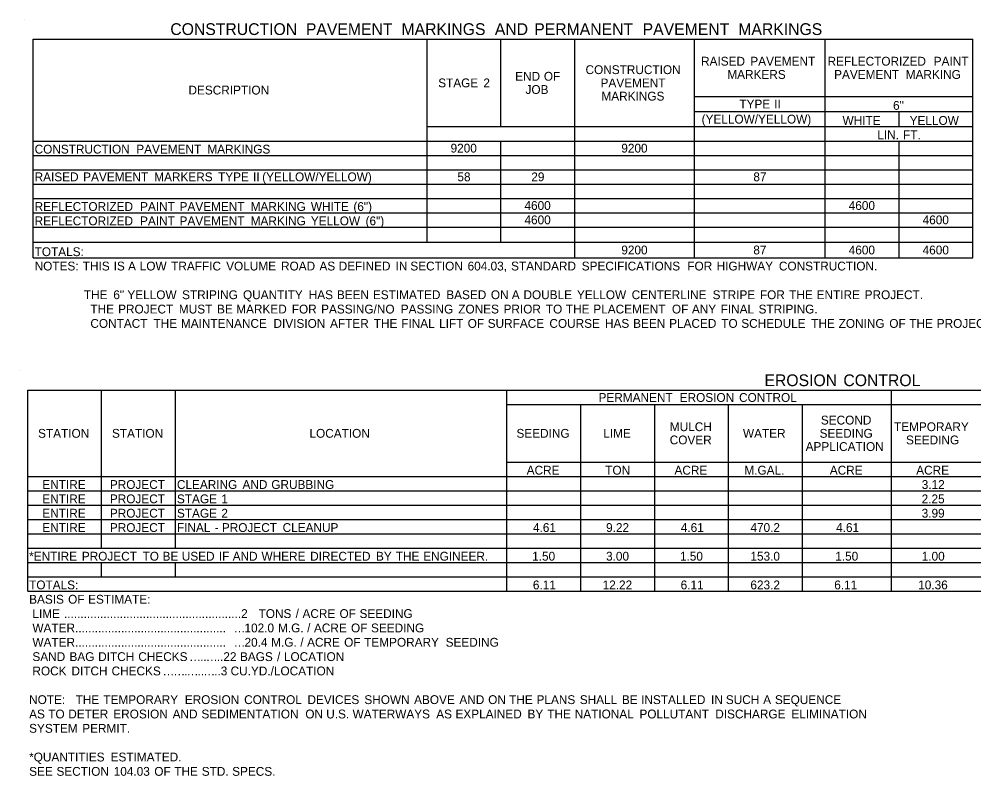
# Model space of a CAD drawing. Extents: x 1940653 to 1945779, y 534266 to 535271.
# Drawn here: x 1940655 to 1941239, y 534297 to 534760 of the extents above; entities that cross this region are included whole.
import ezdxf

# ---------------------------------------------------------------- set-up
doc = ezdxf.new("R2010")
doc.units = 0
doc.layers.add('Default', color=7, linetype='Continuous')
doc.layers.add('R_Logo', color=7, linetype='Continuous')

msp = doc.modelspace()

# ---------------------------------------------------------------- linework, layer by layer
at = {"layer": 'Default'}
for p, q in [((1940663.72, 534748.03), (1941238.48, 534748.03)), ((1940663.72, 534614.21), (1940663.72, 534748.03)), ((1940663.72, 534614.21), (1940663.72, 534748.03)), ((1940904.59, 534623.86), (1940904.59, 534748.03)), ((1940949.78, 534694.5), (1940949.78, 534748.03)), ((1940994.97, 534614.21), (1940994.97, 534748.03)), ((1941068.24, 534614.21), (1941068.24, 534748.03)), ((1941148.1, 534614.21), (1941148.1, 534748.03)), ((1941238.48, 534614.21), (1941238.48, 534748.03)), ((1941068.24, 534712.93), (1941238.48, 534712.93)), ((1941068.24, 534703.71), (1941238.48, 534703.71)), ((1941193.29, 534694.5), (1941193.29, 534703.71)), ((1940904.59, 534694.5), (1941238.48, 534694.5)), ((1940904.59, 534623.86), (1940904.59, 534694.5)), ((1940994.97, 534614.21), (1940994.97, 534694.5)), ((1941068.24, 534614.21), (1941068.24, 534694.5)), ((1940663.72, 534685.72), (1941238.48, 534685.72)), ((1940949.78, 534623.86), (1940949.78, 534685.72)), ((1940949.78, 534623.86), (1940949.78, 534685.72)), ((1941148.1, 534614.21), (1941148.1, 534685.72)), ((1941193.29, 534614.21), (1941193.29, 534685.72)), ((1941193.29, 534614.21), (1941193.29, 534685.72)), ((1940663.72, 534676.95), (1941238.48, 534676.95)), ((1940663.72, 534668.17), (1941238.48, 534668.17)), ((1940663.72, 534659.4), (1941238.48, 534659.4)), ((1940663.72, 534650.62), (1941238.48, 534650.62)), ((1940663.72, 534641.85), (1941238.48, 534641.85)), ((1940663.72, 534633.07), (1941238.48, 534633.07)), ((1940663.72, 534623.86), (1941238.48, 534623.86)), ((1940663.72, 534614.21), (1941238.48, 534614.21)), ((1940660.36, 534533.19), (1941659.39, 534533.19)), ((1940660.36, 534410.34), (1940660.36, 534533.19)), ((1940660.36, 534410.34), (1940660.36, 534533.19)), ((1940705.55, 534436.66), (1940705.55, 534533.19)), ((1940750.74, 534436.66), (1940750.74, 534533.19)), ((1940953.44, 534410.34), (1940953.44, 534533.19)), ((1941188.61, 534524.41), (1941188.61, 534533.19)), ((1941188.61, 534410.34), (1941188.61, 534533.19)), ((1940953.44, 534524.41), (1941659.39, 534524.41)), ((1940998.63, 534410.34), (1940998.63, 534524.41)), ((1941043.82, 534410.34), (1941043.82, 534524.41)), ((1941089.02, 534410.34), (1941089.02, 534524.41)), ((1941134.21, 534410.34), (1941134.21, 534524.41)), ((1940953.44, 534489.31), (1941545.75, 534489.31)), ((1940998.63, 534410.34), (1940998.63, 534489.31)), ((1941043.82, 534419.11), (1941043.82, 534489.31)), ((1941089.02, 534419.11), (1941089.02, 534489.31)), ((1941134.21, 534419.11), (1941134.21, 534489.31)), ((1941188.61, 534419.11), (1941188.61, 534489.31)), ((1940660.36, 534480.54), (1941659.39, 534480.54)), ((1940705.55, 534436.66), (1940705.55, 534480.54)), ((1940750.74, 534436.66), (1940750.74, 534480.54)), ((1940953.44, 534436.66), (1940953.44, 534480.54)), ((1940660.36, 534471.76), (1941659.39, 534471.76)), ((1940660.36, 534462.99), (1941659.39, 534462.99)), ((1940660.36, 534454.21), (1941659.39, 534454.21)), ((1940660.36, 534445.44), (1941659.39, 534445.44)), ((1940660.36, 534436.66), (1941659.39, 534436.66)), ((1940660.36, 534427.89), (1941659.39, 534427.89)), ((1940705.55, 534419.11), (1940705.55, 534427.89)), ((1940705.55, 534419.11), (1940705.55, 534427.89)), ((1940750.74, 534419.11), (1940750.74, 534427.89)), ((1940750.74, 534419.11), (1940750.74, 534427.89)), ((1940953.44, 534410.34), (1940953.44, 534427.89)), ((1940660.36, 534419.11), (1941188.61, 534419.11)), ((1940998.63, 534419.11), (1941188.61, 534419.11)), ((1941188.61, 534419.11), (1941435.19, 534419.11)), ((1940660.36, 534410.34), (1941659.39, 534410.34))]:
    msp.add_line(p, q, dxfattribs=at)
at = {"layer": 'R_Logo'}
for p, q in [((1940658.45, 534760.31), (1940658.45, 534760.31)), ((1940655.09, 534545.47), (1940655.09, 534545.47))]:
    msp.add_line(p, q, dxfattribs=at)

# ---------------------------------------------------------------- texts
at = {"layer": 'Default'}
for s, height, p in [('CONSTRUCTION', 7.2, (1940747.58, 534750.57)), (' PAVEMENT', 7.2, (1940827.82, 534750.57)), (' MARKINGS', 7.2, (1940886.31, 534750.57)), (' AND', 7.2, (1940943.38, 534750.57)), (' PERMANENT', 7.2, (1940967.47, 534750.57)), (' PAVEMENT', 7.2, (1941033.78, 534750.57)), (' MARKINGS', 7.2, (1941092.27, 534750.57)), ('RAISED', 5.4, (1941072.17, 534731.83)), (' PAVEMENT', 5.4, (1941100.3, 534731.83)), ('REFLECTORIZED', 5.4, (1941149.54, 534731.83)), (' PAINT', 5.4, (1941212.46, 534731.83)), ('END', 5.4, (1940958.49, 534722.61)), (' OF', 5.4, (1940974.04, 534722.61)), ('CONSTRUCTION', 5.4, (1941001.52, 534726.66)), ('MARKERS', 5.4, (1941088.23, 534723.73)), ('PAVEMENT', 5.4, (1941153.56, 534723.73)), (' MARKING', 5.4, (1941195.33, 534723.73)), ('STAGE', 5.4, (1940911.42, 534718.56)), (' 2', 5.4, (1940937.04, 534718.56)), ('PAVEMENT', 5.4, (1941010.72, 534718.56)), ('DESCRIPTION', 5.4, (1940758.67, 534714.18)), ('JOB', 5.4, (1940964.81, 534714.51)), ('MARKINGS', 5.4, (1941011.25, 534710.46)), ('TYPE', 5.4, (1941095.6, 534705.62)), (' II', 5.4, (1941114.94, 534705.62)), ('6"', 5.4, (1941189.59, 534704.79)), ('(YELLOW/YELLOW)', 5.4, (1941072.53, 534696.41)), ('WHITE', 5.4, (1941158.72, 534695.58)), ('YELLOW', 5.4, (1941199.75, 534695.58)), ('LIN.', 5.4, (1941179.98, 534686.8)), (' FT.', 5.4, (1941193.71, 534686.8)), ('CONSTRUCTION', 5.4, (1940664.59, 534678.03)), (' PAVEMENT', 5.4, (1940724.76, 534678.03)), (' MARKINGS', 5.4, (1940768.21, 534678.03)), ('9200', 5.4, (1940918.98, 534678.64)), ('9200', 5.4, (1941023.4, 534678.64)), ('RAISED', 5.4, (1940664.59, 534661.09)), (' PAVEMENT', 5.4, (1940692.28, 534661.09)), (' MARKERS', 5.4, (1940735.74, 534661.09)), (' TYPE', 5.4, (1940774.76, 534661.09)), (' II', 5.4, (1940796.16, 534661.09)), (' (YELLOW/YELLOW)', 5.4, (1940801.77, 534661.09)), ('58', 5.4, (1940923.16, 534661.09)), ('29', 5.4, (1940968.35, 534661.09)), ('87', 5.4, (1941104.15, 534661.09)), ('REFLECTORIZED', 5.4, (1940664.59, 534642.93)), (' PAINT', 5.4, (1940727.08, 534642.93)), (' PAVEMENT', 5.4, (1940751.24, 534642.93)), (' MARKING', 5.4, (1940794.7, 534642.93)), (' WHITE', 5.4, (1940831.53, 534642.93)), (' (6")', 5.4, (1940857.53, 534642.93)), ('4600', 5.4, (1940964.17, 534643.54)), ('4600', 5.4, (1941162.48, 534643.54)), ('4600', 5.4, (1940964.17, 534634.76)), ('4600', 5.4, (1941207.68, 534634.76)), ('REFLECTORIZED', 5.4, (1940664.59, 534634.15)), (' PAINT', 5.4, (1940727.08, 534634.15)), (' PAVEMENT', 5.4, (1940751.24, 534634.15)), (' MARKING', 5.4, (1940794.7, 534634.15)), (' YELLOW', 5.4, (1940831.53, 534634.15)), (' (6")', 5.4, (1940864.99, 534634.15)), ('TOTALS:', 5.4, (1940664.59, 534615.29)), ('9200', 5.4, (1941023.4, 534616.33)), ('87', 5.4, (1941104.14, 534616.33)), ('4600', 5.4, (1941162.49, 534616.33)), ('4600', 5.4, (1941207.68, 534616.33)), ('NOTES:', 5.4, (1940664.59, 534606.51)), (' THIS', 5.4, (1940692.03, 534606.51)), (' IS', 5.4, (1940710.91, 534606.51)), (' A', 5.4, (1940719.74, 534606.51)), (' LOW', 5.4, (1940726.88, 534606.51)), (' TRAFFIC', 5.4, (1940746.08, 534606.51)), (' VOLUME', 5.4, (1940779.73, 534606.51)), (' ROAD', 5.4, (1940813.28, 534606.51)), (' AS', 5.4, (1940836.78, 534606.51)), (' DEFINED', 5.4, (1940848.54, 534606.51)), (' IN', 5.4, (1940883.36, 534606.51)), (' SECTION', 5.4, (1940892.38, 534606.51)), (' 604.03,', 5.4, (1940927.39, 534606.51)), (' STANDARD', 5.4, (1940953.98, 534606.51)), (' SPECIFICATIONS', 5.4, (1940997.18, 534606.51)), (' FOR', 5.4, (1941061.77, 534606.51)), (' HIGHWAY', 5.4, (1941079.69, 534606.51)), (' CONSTRUCTION.', 5.4, (1941117.78, 534606.51)), ('               THE', 5.4, (1940664.59, 534588.96)), (' 6"', 5.4, (1940710.71, 534588.96)), (' YELLOW', 5.4, (1940719.32, 534588.96)), (' STRIPING', 5.4, (1940752.78, 534588.96)), (' QUANTITY', 5.4, (1940790.03, 534588.96)), (' HAS', 5.4, (1940830.22, 534588.96)), (' BEEN', 5.4, (1940847.44, 534588.96)), (' ESTIMATED', 5.4, (1940869.46, 534588.96)), (' BASED', 5.4, (1940914.34, 534588.96)), (' ON', 5.4, (1940941.62, 534588.96)), (' A', 5.4, (1940954.41, 534588.96)), (' DOUBLE', 5.4, (1940961.55, 534588.96)), (' YELLOW', 5.4, (1940994.27, 534588.96)), (' CENTERLINE', 5.4, (1941027.73, 534588.96)), (' STRIPE', 5.4, (1941077.22, 534588.96)), (' FOR', 5.4, (1941106.16, 534588.96)), (' THE', 5.4, (1941124.08, 534588.96)), (' ENTIRE', 5.4, (1941140.87, 534588.96)), (' PROJECT.', 5.4, (1941170.23, 534588.96)), ('   THE', 5.4, (1940692.67, 534580.19)), (' PROJECT', 5.4, (1940713.65, 534580.19)), (' MUST', 5.4, (1940750.81, 534580.19)), (' BE', 5.4, (1940774.13, 534580.19)), (' MARKED', 5.4, (1940785.89, 534580.19)), (' FOR', 5.4, (1940819.87, 534580.19)), (' PASSING/NO', 5.4, (1940837.79, 534580.19)), (' PASSING', 5.4, (1940886.51, 534580.19)), (' ZONES', 5.4, (1940921.68, 534580.19)), (' PRIOR', 5.4, (1940949.37, 534580.19)), (' TO', 5.4, (1940975.26, 534580.19)), (' THE', 5.4, (1940987.5, 534580.19)), (' PLACEMENT', 5.4, (1941004.28, 534580.19)), (' OF', 5.4, (1941052.35, 534580.19)), (' ANY', 5.4, (1941064.57, 534580.19)), (' FINAL', 5.4, (1941082.13, 534580.19)), (' STRIPING.', 5.4, (1941105.34, 534580.19)), ('   CONTACT', 5.4, (1940692.67, 534571.41)), (' THE', 5.4, (1940735.28, 534571.41)), (' MAINTENANCE', 5.4, (1940752.06, 534571.41)), (' DIVISION', 5.4, (1940808.67, 534571.41)), (' AFTER', 5.4, (1940843.27, 534571.41)), (' THE', 5.4, (1940870, 534571.41)), (' FINAL', 5.4, (1940886.79, 534571.41)), (' LIFT', 5.4, (1940909.99, 534571.41)), (' OF', 5.4, (1940927.45, 534571.41)), (' SURFACE', 5.4, (1940939.67, 534571.41)), (' COURSE', 5.4, (1940977.42, 534571.41)), (' HAS', 5.4, (1941011.4, 534571.41)), (' BEEN', 5.4, (1941028.62, 534571.41)), (' PLACED', 5.4, (1941050.65, 534571.41)), (' TO', 5.4, (1941082.53, 534571.41)), (' SCHEDULE', 5.4, (1941094.77, 534571.41)), (' THE', 5.4, (1941137.55, 534571.41)), (' ZONING', 5.4, (1941154.34, 534571.41)), (' OF', 5.4, (1941185.3, 534571.41)), (' THE', 5.4, (1941197.53, 534571.41)), (' PROJECT.', 5.4, (1941214.31, 534571.41)), ('EROSION', 7.2, (1941110.96, 534535.73)), (' CONTROL', 7.2, (1941156.55, 534535.73)), ('PERMANENT', 5.4, (1941009.48, 534526.1)), (' EROSION', 5.4, (1941057.11, 534526.1)), (' CONTROL', 5.4, (1941093.4, 534526.1)), ('SECOND', 5.4, (1941145.45, 534512.26)), ('MULCH', 5.4, (1941053.09, 534508.21)), ('TEMPORARY', 5.4, (1941190.17, 534508.21)), ('STATION', 5.4, (1940666.7, 534504.16)), ('STATION', 5.4, (1940711.89, 534504.16)), ('LOCATION', 5.4, (1940832.69, 534504.16)), ('SEEDING', 5.4, (1940959.28, 534504.16)), ('LIME', 5.4, (1941012.4, 534504.16)), ('WATER', 5.4, (1941097.8, 534504.16)), ('SEEDING', 5.4, (1941144.66, 534504.16)), ('COVER', 5.4, (1941053.02, 534500.11)), ('APPLICATION', 5.4, (1941136.14, 534496.06)), ('SEEDING', 5.4, (1941197.52, 534500.11)), ('ACRE', 5.4, (1940965.53, 534481.62)), ('TON', 5.4, (1941013.57, 534481.62)), ('ACRE', 5.4, (1941055.92, 534481.62)), ('M.GAL.', 5.4, (1941098.67, 534481.62)), ('ACRE', 5.4, (1941150.91, 534481.62)), ('ACRE', 5.4, (1941203.77, 534481.62)), ('ENTIRE', 5.4, (1940669.32, 534472.84)), ('PROJECT', 5.4, (1940710.61, 534472.84)), ('CLEARING', 5.4, (1940751.62, 534472.84)), (' AND', 5.4, (1940789.72, 534472.84)), (' GRUBBING', 5.4, (1940807.34, 534472.84)), ('3.12', 5.4, (1941207.14, 534472.84)), ('ENTIRE', 5.4, (1940669.32, 534464.07)), ('PROJECT', 5.4, (1940710.61, 534464.07)), ('STAGE', 5.4, (1940751.62, 534464.07)), (' 1', 5.4, (1940776.79, 534464.07)), ('2.25', 5.4, (1941207.09, 534464.07)), ('ENTIRE', 5.4, (1940669.32, 534455.29)), ('PROJECT', 5.4, (1940710.61, 534455.29)), ('STAGE', 5.4, (1940751.62, 534455.29)), (' 2', 5.4, (1940776.79, 534455.29)), ('3.99', 5.4, (1941207.11, 534455.29)), ('ENTIRE', 5.4, (1940669.32, 534446.52)), ('PROJECT', 5.4, (1940710.61, 534446.52)), ('FINAL', 5.4, (1940751.62, 534446.52)), (' -', 5.4, (1940772.73, 534446.52)), (' PROJECT', 5.4, (1940777.1, 534446.52)), (' CLEANUP', 5.4, (1940814.26, 534446.52)), ('4.61', 5.4, (1940969.39, 534446.52)), ('9.22', 5.4, (1941014.09, 534446.52)), ('4.61', 5.4, (1941059.77, 534446.52)), ('470.2', 5.4, (1941102.37, 534446.52)), ('4.61', 5.4, (1941154.76, 534446.52)), ('*ENTIRE', 5.4, (1940661.23, 534428.97)), (' PROJECT', 5.4, (1940691.44, 534428.97)), (' TO', 5.4, (1940728.6, 534428.97)), (' BE', 5.4, (1940740.83, 534428.97)), (' USED', 5.4, (1940752.59, 534428.97)), (' IF', 5.4, (1940775.25, 534428.97)), (' AND', 5.4, (1940783.71, 534428.97)), (' WHERE', 5.4, (1940801.33, 534428.97)), (' DIRECTED', 5.4, (1940831.11, 534428.97)), (' BY', 5.4, (1940871.37, 534428.97)), (' THE', 5.4, (1940883.47, 534428.97)), (' ENGINEER.', 5.4, (1940900.26, 534428.97)), ('1.50', 5.4, (1940968.88, 534428.97)), ('3.00', 5.4, (1941014.07, 534428.97)), ('1.50', 5.4, (1941059.26, 534428.97)), ('153.0', 5.4, (1941102.36, 534428.97)), ('1.50', 5.4, (1941154.25, 534428.97)), ('1.00', 5.4, (1941207.12, 534428.97)), ('TOTALS:', 5.4, (1940661.23, 534411.42)), ('6.11', 5.4, (1940969.31, 534411.42)), ('12.22', 5.4, (1941011.98, 534411.42)), ('6.11', 5.4, (1941059.69, 534411.42)), ('623.2', 5.4, (1941102.36, 534411.42)), ('6.11', 5.4, (1941153.63, 534411.42)), ('10.36', 5.4, (1941204.98, 534411.42)), ('BASIS', 5.4, (1940661.23, 534402.64)), (' OF', 5.4, (1940683.07, 534402.64)), (' ESTIMATE:', 5.4, (1940695.3, 534402.64)), (' LIME', 5.4, (1940661.23, 534393.87)), (' ......................................................2', 5.4, (1940680.53, 534393.87)), (' TONS', 5.4, (1940799.55, 534393.87)), (' /', 5.4, (1940822.21, 534393.87)), (' ACRE', 5.4, (1940826.41, 534393.87)), (' OF', 5.4, (1940849.06, 534393.87)), (' SEEDING', 5.4, (1940861.29, 534393.87)), (' WATER..............................................', 5.4, (1940661.23, 534385.09)), ('102.0', 5.4, (1940792.95, 534385.09)), (' M.G.', 5.4, (1940811.45, 534385.09)), (' /', 5.4, (1940829.23, 534385.09)), (' ACRE', 5.4, (1940833.43, 534385.09)), (' OF', 5.4, (1940856.09, 534385.09)), (' SEEDING', 5.4, (1940868.31, 534385.09)), ('…', 5.4, (1940786.29, 534385.09)), (' WATER..............................................', 5.4, (1940661.23, 534376.32)), ('20.4', 5.4, (1940792.95, 534376.32)), (' M.G.', 5.4, (1940807.26, 534376.32)), (' /', 5.4, (1940825.04, 534376.32)), (' ACRE', 5.4, (1940829.23, 534376.32)), (' OF', 5.4, (1940851.89, 534376.32)), (' TEMPORARY', 5.4, (1940864.12, 534376.32)), (' SEEDING', 5.4, (1940913.95, 534376.32)), (' SAND', 5.4, (1940661.23, 534367.54)), (' BAG', 5.4, (1940683.89, 534367.54)), (' DITCH', 5.4, (1940701.45, 534367.54)), (' CHECKS', 5.4, (1940725.99, 534367.54)), ('..22', 5.4, (1940775.99, 534367.54)), ('…', 5.4, (1940786.29, 534376.32)), (' BAGS', 5.4, (1940788.17, 534367.54)), (' /', 5.4, (1940810.84, 534367.54)), (' LOCATION', 5.4, (1940815.03, 534367.54)), ('…', 5.4, (1940759.14, 534367.54)), ('..', 5.4, (1940765.8, 534367.54)), ('…', 5.4, (1940769.33, 534367.54)), (' ROCK', 5.4, (1940661.23, 534358.77)), (' DITCH', 5.4, (1940685.11, 534358.77)), (' CHECKS', 5.4, (1940709.65, 534358.77)), ('..3', 5.4, (1940774.41, 534358.77)), (' CU.YD./LOCATION', 5.4, (1940782.45, 534358.77)), ('…', 5.4, (1940742.8, 534358.77)), ('…', 5.4, (1940749.46, 534358.77)), ('.', 5.4, (1940756.12, 534358.77)), ('…', 5.4, (1940757.56, 534358.77)), ('..', 5.4, (1940764.22, 534358.77)), ('…', 5.4, (1940767.75, 534358.77)), ('NOTE:', 5.4, (1940661.23, 534341.22)), ('   THE', 5.4, (1940683.63, 534341.22)), (' TEMPORARY', 5.4, (1940704.61, 534341.22)), (' EROSION', 5.4, (1940754.44, 534341.22)), (' CONTROL', 5.4, (1940790.72, 534341.22)), (' DEVICES', 5.4, (1940829.44, 534341.22)), (' SHOWN', 5.4, (1940864.26, 534341.22)), (' ABOVE', 5.4, (1940894.66, 534341.22)), (' AND', 5.4, (1940922.36, 534341.22)), (' ON', 5.4, (1940939.98, 534341.22)), (' THE', 5.4, (1940952.78, 534341.22)), (' PLANS', 5.4, (1940969.56, 534341.22)), (' SHALL', 5.4, (1940996.01, 534341.22)), (' BE', 5.4, (1941021.74, 534341.22)), (' INSTALLED', 5.4, (1941033.5, 534341.22)), (' IN', 5.4, (1941076.28, 534341.22)), (' SUCH', 5.4, (1941085.31, 534341.22)), (' A', 5.4, (1941108.17, 534341.22)), (' SEQUENCE', 5.4, (1941115.32, 534341.22)), ('AS', 5.4, (1940661.23, 534332.44)), (' TO', 5.4, (1940670.91, 534332.44)), (' DETER', 5.4, (1940683.14, 534332.44)), (' EROSION', 5.4, (1940710.71, 534332.44)), (' AND', 5.4, (1940746.99, 534332.44)), (' SEDIMENTATION', 5.4, (1940764.61, 534332.44)), (' ON', 5.4, (1940828.14, 534332.44)), (' U.S.', 5.4, (1940840.93, 534332.44)), (' WATERWAYS', 5.4, (1940857.04, 534332.44)), (' AS', 5.4, (1940908.21, 534332.44)), (' EXPLAINED', 5.4, (1940919.98, 534332.44)), (' BY', 5.4, (1940964.02, 534332.44)), (' THE', 5.4, (1940976.13, 534332.44)), (' NATIONAL', 5.4, (1940992.91, 534332.44)), (' POLLUTANT', 5.4, (1941032.48, 534332.44)), (' DISCHARGE', 5.4, (1941078.86, 534332.44)), (' ELIMINATION', 5.4, (1941125.42, 534332.44)), ('SYSTEM', 5.4, (1940661.23, 534323.67)), (' PERMIT.', 5.4, (1940691.7, 534323.67)), ('*QUANTITIES', 5.4, (1940661.23, 534306.12)), (' ESTIMATED.', 5.4, (1940709.05, 534306.12)), ('SEE', 5.4, (1940661.23, 534297.34)), (' SECTION', 5.4, (1940675.93, 534297.34)), (' 104.03', 5.4, (1940710.95, 534297.34)), (' OF', 5.4, (1940735.77, 534297.34)), (' THE', 5.4, (1940748, 534297.34)), (' STD.', 5.4, (1940764.78, 534297.34)), (' SPECS.', 5.4, (1940783.4, 534297.34))]:
    msp.add_text(s, height=height, dxfattribs=at).set_placement(p)

doc.saveas('drawing.dxf')
